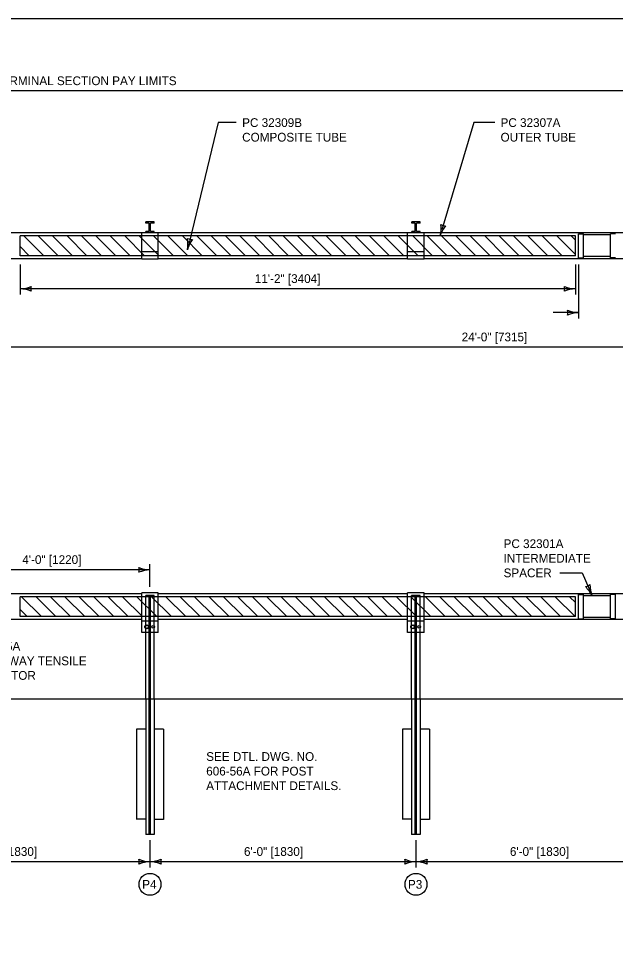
# Model space of a CAD drawing. Extents: x 49991.4 to 50021, y 49987.6 to 50011.4.
# Drawn here: x 50008.63 to 50012.72, y 49992.64 to 49999 of the extents above; entities that cross this region are included whole.
import ezdxf

# ---------------------------------------------------------------- set-up
doc = ezdxf.new("R2010")
doc.units = 0
for name, color, linetype in [('Level 1', 7, 'Continuous'), ('Level 2', 7, 'Continuous'), ('Level 3', 7, 'Continuous'), ('Level 4', 7, 'Continuous'), ('Level 5', 7, 'Continuous')]:
    doc.layers.add(name, color=color, linetype=linetype)

msp = doc.modelspace()

# ---------------------------------------------------------------- linework, layer by layer
at = {"layer": 'Level 1'}
for p, q in [((50009.4981, 49997.5971), (50009.4981, 49997.6062)), ((50009.5571, 49997.6062), (50009.4981, 49997.6062)), ((50009.5231, 49997.5971), (50009.4981, 49997.5971)), ((50009.5231, 49997.5395), (50009.5231, 49997.5971)), ((50009.5322, 49997.5395), (50009.5322, 49997.5971)), ((50009.5571, 49997.5971), (50009.5322, 49997.5971)), ((50009.5571, 49997.5971), (50009.5571, 49997.6062)), ((50011.3214, 49997.597), (50011.3214, 49997.6061)), ((50011.3803, 49997.6061), (50011.3214, 49997.6061)), ((50011.3462, 49997.597), (50011.3214, 49997.597)), ((50011.3462, 49997.5394), (50011.3462, 49997.597)), ((50011.3554, 49997.5394), (50011.3554, 49997.597)), ((50011.3803, 49997.597), (50011.3554, 49997.597)), ((50011.3803, 49997.597), (50011.3803, 49997.6061)), ((50015.4527, 49997.53), (50008.363, 49997.5304)), ((50009.5231, 49997.5395), (50009.4981, 49997.5395)), ((50009.4981, 49997.5303), (50009.4981, 49997.5395)), ((50009.5571, 49997.5395), (50009.5322, 49997.5395)), ((50009.5571, 49997.5303), (50009.5571, 49997.5395)), ((50011.3462, 49997.5394), (50011.3214, 49997.5394)), ((50011.3214, 49997.5302), (50011.3214, 49997.5394)), ((50011.3803, 49997.5394), (50011.3554, 49997.5394)), ((50011.3803, 49997.5302), (50011.3803, 49997.5394)), ((50009.5845, 49997.4006), (50009.4706, 49997.4006)), ((50009.4706, 49997.35), (50009.4706, 49997.4006)), ((50009.5845, 49997.35), (50009.5845, 49997.4006)), ((50011.4076, 49997.4005), (50011.2937, 49997.4005)), ((50011.2937, 49997.3499), (50011.2937, 49997.4004)), ((50011.4076, 49997.3499), (50011.4076, 49997.4005)), ((50009.4706, 49997.3533), (50008.363, 49997.3532)), ((50009.5845, 49997.35), (50009.4706, 49997.35)), ((50011.2937, 49997.3531), (50009.5845, 49997.3533)), ((50011.4076, 49997.3499), (50011.2937, 49997.3499)), ((50013.1168, 49997.3529), (50011.4076, 49997.3531)), ((50009.4706, 49995.0567), (50008.3628, 49995.0567)), ((50009.4706, 49994.7908), (50009.4706, 49995.0629)), ((50009.5845, 49995.0629), (50009.4706, 49995.0629)), ((50009.5845, 49994.7908), (50009.5845, 49995.0629)), ((50011.2938, 49995.0567), (50009.5845, 49995.0567)), ((50011.2937, 49994.7908), (50011.2937, 49995.0629)), ((50011.4076, 49995.0629), (50011.2937, 49995.0629)), ((50011.4076, 49994.7908), (50011.4076, 49995.0629)), ((50013.1169, 49995.0567), (50011.4076, 49995.0567)), ((50009.4706, 49994.8794), (50008.3628, 49994.8794)), ((50009.5845, 49994.8683), (50009.4706, 49994.8683)), ((50011.2937, 49994.8794), (50009.5845, 49994.8794)), ((50011.4076, 49994.8683), (50011.2937, 49994.8683)), ((50013.1169, 49994.8794), (50011.4076, 49994.8794)), ((50009.5845, 49994.7908), (50009.4706, 49994.7908)), ((50009.498, 49994.335), (50009.498, 49994.7908)), ((50009.5571, 49994.335), (50009.5571, 49994.7908)), ((50011.4076, 49994.7908), (50011.2937, 49994.7908)), ((50011.3212, 49994.335), (50011.3212, 49994.7908)), ((50011.3803, 49994.335), (50011.3803, 49994.7908)), ((49999.9212, 49994.335), (50016.2933, 49994.335))]:
    msp.add_line(p, q, dxfattribs=at)
for points in [[(49999.3835, 49998.9992), (50016.7501, 49998.9992), (50016.7501, 49987.7988), (49999.3835, 49987.7988)], [(50009.4994, 49994.8404), (50009.5118, 49994.8402), (50009.5179, 49994.8294), (50009.5115, 49994.8188), (50009.4993, 49994.8191), (50009.4932, 49994.8297)], [(50011.3226, 49994.8404), (50011.3349, 49994.8402), (50011.3409, 49994.8294), (50011.3347, 49994.8188), (50011.3224, 49994.8191), (50011.3164, 49994.8297)]]:
    msp.add_lwpolyline(points, close=True, dxfattribs=at)
for centre, radius in [((50009.5055, 49994.8296), 0.0135), ((50009.5496, 49994.8296), 0.00904), ((50011.3286, 49994.8296), 0.0135), ((50011.3727, 49994.8296), 0.00904)]:
    msp.add_circle(centre, radius, dxfattribs=at)
at = {"layer": 'Level 2'}
for centre in [(50009.5276, 49993.0644), (50011.3508, 49993.0644)]:
    msp.add_circle(centre, 0.075, dxfattribs=at)
at = {"layer": 'Level 3'}
for p, q in [((50015.9211, 49998.5028), (50001.3238, 49998.5028)), ((50009.9948, 49998.2858), (50009.784, 49997.4145)), ((50010.1194, 49998.2858), (50009.9948, 49998.2858)), ((50011.7468, 49998.2858), (50011.5284, 49997.5504)), ((50011.8907, 49998.2858), (50011.7468, 49998.2858)), ((50008.6371, 49997.3132), (50008.6371, 49997.1066)), ((50012.4441, 49997.313), (50012.4441, 49997.1066)), ((50012.4652, 49997.313), (50012.4652, 49996.9436)), ((50012.4441, 49997.1466), (50008.6371, 49997.1466)), ((50012.4652, 49996.9836), (50012.2918, 49996.9836)), ((50015.6047, 49996.7466), (50008.3123, 49996.7466)), ((50009.5276, 49995.2202), (50008.3121, 49995.2202)), ((50009.5276, 49995.1029), (50009.5276, 49995.2602)), ((50012.3372, 49995.1995), (50012.4891, 49995.1995)), ((50012.4891, 49995.1995), (50012.5578, 49995.0423)), ((50009.5276, 49993.3671), (50009.5276, 49993.1794)), ((50011.3508, 49993.3671), (50011.3508, 49993.1794)), ((50009.5278, 49993.2194), (50007.7048, 49993.2194)), ((50011.3508, 49993.2194), (50009.5278, 49993.2194)), ((50013.1738, 49993.2194), (50011.3508, 49993.2194))]:
    msp.add_line(p, q, dxfattribs=at)
for centre, radius, start, end in [((50011.2901, 49997.5655), 0.233, 346.28513, 5.53498), ((50011.7268, 49997.4383), 0.2223, 140.91383, 161.09734), ((50011.553, 49997.6332), 0.0548, 235.59664, 271.319), ((50009.5551, 49997.4592), 0.233, 349.0074, 8.25725), ((50009.9973, 49997.3528), 0.2223, 143.6361, 163.81961), ((50009.8144, 49997.5393), 0.0548, 238.31891, 274.04127), ((50008.6256, 49997.3793), 0.233, 272.82731, 292.07716), ((50008.6279, 49996.9245), 0.2223, 67.45601, 87.63952), ((50008.7653, 49997.1466), 0.0548, 162.13882, 197.86118), ((50012.4533, 49997.3687), 0.2223, 247.45601, 267.63952), ((50012.3159, 49997.1466), 0.0548, 342.13882, 17.86118), ((50012.4556, 49996.9139), 0.233, 92.82731, 112.07716), ((50012.337, 49996.9836), 0.0548, 342.13882, 17.86118), ((50012.4767, 49997.2163), 0.233, 247.92284, 267.17269), ((50012.4744, 49996.7614), 0.2223, 92.36048, 112.54399), ((50009.5368, 49995.4423), 0.2223, 247.45601, 267.63952), ((50009.3994, 49995.2202), 0.0548, 342.13882, 17.86118), ((50009.5391, 49994.9875), 0.233, 92.82731, 112.07716), ((50012.5065, 49995.1598), 0.0548, 275.75719, 311.47955), ((50012.3492, 49994.9385), 0.233, 26.44568, 45.69553), ((50012.765, 49995.1229), 0.2223, 181.07438, 201.25789), ((50009.5368, 49993.4415), 0.2223, 247.45601, 267.63952), ((50009.3994, 49993.2194), 0.0548, 342.13882, 17.86118), ((50009.5161, 49993.4521), 0.233, 272.82731, 292.07716), ((50009.6558, 49993.2194), 0.0548, 162.13882, 197.86118), ((50011.36, 49993.4415), 0.2223, 247.45601, 267.63952), ((50011.2226, 49993.2194), 0.0548, 342.13882, 17.86118), ((50011.3393, 49993.4521), 0.233, 272.82731, 292.07716), ((50011.479, 49993.2194), 0.0548, 162.13882, 197.86118), ((50009.5391, 49992.9867), 0.233, 92.82731, 112.07716), ((50009.5184, 49992.9973), 0.2223, 67.45601, 87.63952), ((50011.3623, 49992.9867), 0.233, 92.82731, 112.07716), ((50011.3416, 49992.9973), 0.2223, 67.45601, 87.63952)]:
    msp.add_arc(centre, radius, start, end, dxfattribs=at)
at = {"layer": 'Level 4'}
for p, q in [((50008.6371, 49997.3735), (50008.6372, 49997.5103)), ((50012.4442, 49997.5103), (50008.6372, 49997.5103)), ((50009.4706, 49997.4006), (50009.4706, 49997.5303)), ((50009.5845, 49997.4006), (50009.5845, 49997.5303)), ((50011.2937, 49997.4005), (50011.2937, 49997.5302)), ((50011.4076, 49997.4005), (50011.4076, 49997.5302)), ((50012.4441, 49997.3738), (50012.4442, 49997.5103)), ((50012.4652, 49997.3586), (50012.4653, 49997.5245)), ((50012.4653, 49997.5245), (50012.4991, 49997.5245)), ((50012.499, 49997.3586), (50012.4991, 49997.5245)), ((50012.6847, 49997.516), (50012.4991, 49997.516)), ((50012.6847, 49997.3586), (50012.6847, 49997.5245)), ((50012.7185, 49997.5245), (50012.6847, 49997.5245)), ((50012.4441, 49997.3738), (50008.6371, 49997.3734)), ((50012.6847, 49997.3671), (50012.499, 49997.3671)), ((50012.4652, 49997.3586), (50012.499, 49997.3586)), ((50012.7185, 49997.3586), (50012.6847, 49997.3586)), ((50008.6371, 49994.8996), (50008.6371, 49995.0363)), ((50012.4437, 49995.0363), (50008.6371, 49995.0363)), ((50009.5571, 49995.0439), (50009.498, 49995.0439)), ((50009.498, 49994.7908), (50009.498, 49995.0439)), ((50009.5229, 49993.4071), (50009.5229, 49995.0439)), ((50009.532, 49993.4071), (50009.532, 49995.0439)), ((50009.5571, 49994.7908), (50009.5571, 49995.0439)), ((50011.3803, 49995.0439), (50011.3212, 49995.0439)), ((50011.3212, 49994.7908), (50011.3212, 49995.0439)), ((50011.3461, 49993.4071), (50011.3461, 49995.0439)), ((50011.3552, 49993.4071), (50011.3552, 49995.0439)), ((50011.3803, 49994.7908), (50011.3803, 49995.0439)), ((50012.4437, 49994.8996), (50012.4437, 49995.0363)), ((50012.4648, 49994.8852), (50012.4648, 49995.0508)), ((50012.4648, 49995.0508), (50012.4986, 49995.0508)), ((50012.4986, 49994.8852), (50012.4986, 49995.0508)), ((50012.6842, 49995.0423), (50012.4986, 49995.0423)), ((50012.6842, 49994.8852), (50012.6842, 49995.0508)), ((50012.718, 49995.0508), (50012.6842, 49995.0508)), ((50012.718, 49994.8852), (50012.718, 49995.0508)), ((50012.4437, 49994.8996), (50008.6371, 49994.8996)), ((50012.6842, 49994.8937), (50012.4986, 49994.8937)), ((50012.4648, 49994.8852), (50012.4986, 49994.8852)), ((50012.718, 49994.8852), (50012.6842, 49994.8852)), ((50009.498, 49994.335), (50009.498, 49993.4071)), ((50009.5571, 49994.335), (50009.5571, 49993.4071)), ((50011.3212, 49994.335), (50011.3212, 49993.4071)), ((50011.3803, 49994.335), (50011.3803, 49993.4071)), ((50009.498, 49994.127), (50009.4347, 49994.127)), ((50009.4347, 49994.127), (50009.4347, 49993.5085)), ((50009.6204, 49994.127), (50009.5571, 49994.127)), ((50009.6204, 49994.127), (50009.6204, 49993.5085)), ((50011.3212, 49994.127), (50011.2579, 49994.127)), ((50011.2579, 49994.127), (50011.2579, 49993.5085)), ((50011.4435, 49994.127), (50011.3803, 49994.127)), ((50011.4435, 49994.127), (50011.4435, 49993.5085)), ((50009.498, 49993.5119), (50009.4347, 49993.5119)), ((50009.6204, 49993.5085), (50009.5571, 49993.5085)), ((50011.3212, 49993.5119), (50011.2579, 49993.5119)), ((50011.4435, 49993.5085), (50011.3803, 49993.5085)), ((50009.5571, 49993.4071), (50009.498, 49993.4071)), ((50011.3803, 49993.4071), (50011.3212, 49993.4071))]:
    msp.add_line(p, q, dxfattribs=at)
for points in [[(50009.4706, 49997.3533), (50009.5847, 49997.3533)], [(50011.2937, 49997.3531), (50011.4076, 49997.3531)]]:
    msp.add_lwpolyline(points, dxfattribs=at)
at = {"layer": 'Level 5'}
for p, q in [((50008.7993, 49997.3734), (50008.6625, 49997.5103)), ((50008.8982, 49997.3735), (50008.7614, 49997.5102)), ((50008.9969, 49997.3735), (50008.8602, 49997.5103)), ((50009.0958, 49997.3735), (50008.9591, 49997.5103)), ((50009.1946, 49997.3735), (50009.0579, 49997.5103)), ((50009.2935, 49997.3734), (50009.1566, 49997.5103)), ((50009.3923, 49997.3734), (50009.2556, 49997.5103)), ((50009.4911, 49997.3735), (50009.3544, 49997.5102)), ((50009.5899, 49997.3735), (50009.4533, 49997.5103)), ((50009.6886, 49997.3735), (50009.552, 49997.5103)), ((50009.7873, 49997.3735), (50009.6507, 49997.5103)), ((50009.886, 49997.3735), (50009.7494, 49997.5103)), ((50009.9847, 49997.3735), (50009.8481, 49997.5103)), ((50010.0834, 49997.3735), (50009.9468, 49997.5103)), ((50010.1821, 49997.3735), (50010.0455, 49997.5103)), ((50010.2808, 49997.3735), (50010.1442, 49997.5103)), ((50010.3795, 49997.3735), (50010.2429, 49997.5103)), ((50010.4782, 49997.3735), (50010.3416, 49997.5103)), ((50010.5769, 49997.3735), (50010.4403, 49997.5103)), ((50010.6756, 49997.3735), (50010.539, 49997.5103)), ((50010.7743, 49997.3735), (50010.6377, 49997.5103)), ((50010.873, 49997.3735), (50010.7364, 49997.5103)), ((50010.9717, 49997.3735), (50010.8351, 49997.5103)), ((50011.0704, 49997.3735), (50010.9338, 49997.5103)), ((50011.1691, 49997.3735), (50011.0325, 49997.5103)), ((50011.2678, 49997.3735), (50011.1312, 49997.5103)), ((50011.3665, 49997.3735), (50011.2299, 49997.5103)), ((50011.4652, 49997.3735), (50011.3286, 49997.5103)), ((50011.5639, 49997.3735), (50011.4273, 49997.5103)), ((50011.6626, 49997.3735), (50011.526, 49997.5103)), ((50011.7613, 49997.3735), (50011.6247, 49997.5103)), ((50011.86, 49997.3735), (50011.7234, 49997.5103)), ((50011.9587, 49997.3735), (50011.8221, 49997.5103)), ((50012.0574, 49997.3735), (50011.9208, 49997.5103)), ((50012.1561, 49997.3735), (50012.0195, 49997.5103)), ((50012.2548, 49997.3735), (50012.1182, 49997.5103)), ((50012.3535, 49997.3735), (50012.2169, 49997.5103)), ((50012.4441, 49997.3816), (50012.3156, 49997.5103)), ((50012.4442, 49997.4804), (50012.4143, 49997.5103)), ((50008.7004, 49997.3735), (50008.6372, 49997.4365)), ((50008.7845, 49994.8996), (50008.6478, 49995.0363)), ((50008.8833, 49994.8996), (50008.7466, 49995.0363)), ((50008.9821, 49994.8996), (50008.8455, 49995.0363)), ((50009.081, 49994.8996), (50008.9444, 49995.0363)), ((50009.1798, 49994.8996), (50009.0432, 49995.0363)), ((50009.2787, 49994.8996), (50009.1419, 49995.0363)), ((50009.3774, 49994.8996), (50009.2409, 49995.0363)), ((50009.4764, 49994.8996), (50009.3397, 49995.0363)), ((50009.5752, 49994.8996), (50009.4385, 49995.0363)), ((50009.674, 49994.8996), (50009.5373, 49995.0363)), ((50009.7729, 49994.8996), (50009.6361, 49995.0363)), ((50009.8717, 49994.8996), (50009.735, 49995.0363)), ((50009.9705, 49994.8996), (50009.8337, 49995.0363)), ((50010.0693, 49994.8996), (50009.9327, 49995.0363)), ((50010.1681, 49994.8996), (50010.0314, 49995.0363)), ((50010.267, 49994.8996), (50010.1302, 49995.0363)), ((50010.3657, 49994.8996), (50010.2292, 49995.0363)), ((50010.4646, 49994.8996), (50010.3279, 49995.0363)), ((50010.5635, 49994.8996), (50010.4269, 49995.0363)), ((50010.6623, 49994.8996), (50010.5255, 49995.0363)), ((50010.7611, 49994.8996), (50010.6245, 49995.0363)), ((50010.8601, 49994.8996), (50010.7233, 49995.0363)), ((50010.9588, 49994.8996), (50010.8221, 49995.0363)), ((50011.0576, 49994.8996), (50010.921, 49995.0363)), ((50011.1564, 49994.8996), (50011.0198, 49995.0363)), ((50011.2553, 49994.8996), (50011.1187, 49995.0363)), ((50011.3542, 49994.8996), (50011.2174, 49995.0363)), ((50011.453, 49994.8996), (50011.3164, 49995.0363)), ((50011.5519, 49994.8996), (50011.4152, 49995.0363)), ((50011.6506, 49994.8996), (50011.514, 49995.0363)), ((50011.7495, 49994.8996), (50011.6128, 49995.0363)), ((50011.8483, 49994.8996), (50011.7117, 49995.0363)), ((50011.9472, 49994.8996), (50011.8104, 49995.0363)), ((50012.046, 49994.8996), (50011.9093, 49995.0363)), ((50012.1448, 49994.8996), (50012.0083, 49995.0363)), ((50012.2438, 49994.8996), (50012.107, 49995.0363)), ((50012.3425, 49994.8996), (50012.2058, 49995.0363)), ((50012.4414, 49994.8996), (50012.3047, 49995.0363)), ((50012.4437, 49994.9963), (50012.4036, 49995.0363)), ((50008.6856, 49994.8996), (50008.6371, 49994.9482))]:
    msp.add_line(p, q, dxfattribs=at)

# ---------------------------------------------------------------- texts
at = {"layer": 'Level 2'}
for s, p in [('48\'-2" [14.68 m] OPTIONAL BOX BEAM TERMINAL SECTION PAY LIMITS', (50007.0088, 49998.5428)), ('PC 32309B', (50010.1594, 49998.2558)), ('PC 32307A', (50011.9307, 49998.2558)), ('COMPOSITE TUBE', (50010.1594, 49998.1558)), ('OUTER TUBE', (50011.9307, 49998.1558)), ('11\'-2" [3404]', (50010.2462, 49997.1866)), ('24\'-0" [7315]', (50011.6641, 49996.7866)), ('PC 32301A', (50011.9515, 49995.3695)), ('4\'-0" [1220]', (50008.6523, 49995.2602)), ('INTERMEDIATE', (50011.9515, 49995.2695)), ('SPACER', (50011.9515, 49995.1695)), ('PC 32305A', (50008.2282, 49994.6665)), ('BREAKAWAY TENSILE', (50008.2282, 49994.5665)), ('CONNECTOR', (50008.2282, 49994.4665)), ('SEE DTL. DWG. NO.', (50009.913, 49993.9105)), ('606-56A FOR POST', (50009.913, 49993.8105)), ('ATTACHMENT DETAILS.', (50009.913, 49993.7105)), ('6\'-0" [1830]', (50008.3488, 49993.2594)), ('6\'-0" [1830]', (50010.1718, 49993.2594)), ('6\'-0" [1830]', (50011.9948, 49993.2594)), ('P4', (50009.4742, 49993.0344)), ('P3', (50011.2962, 49993.0344))]:
    msp.add_text(s, height=0.06, dxfattribs=at).set_placement(p)

doc.saveas('drawing.dxf')
